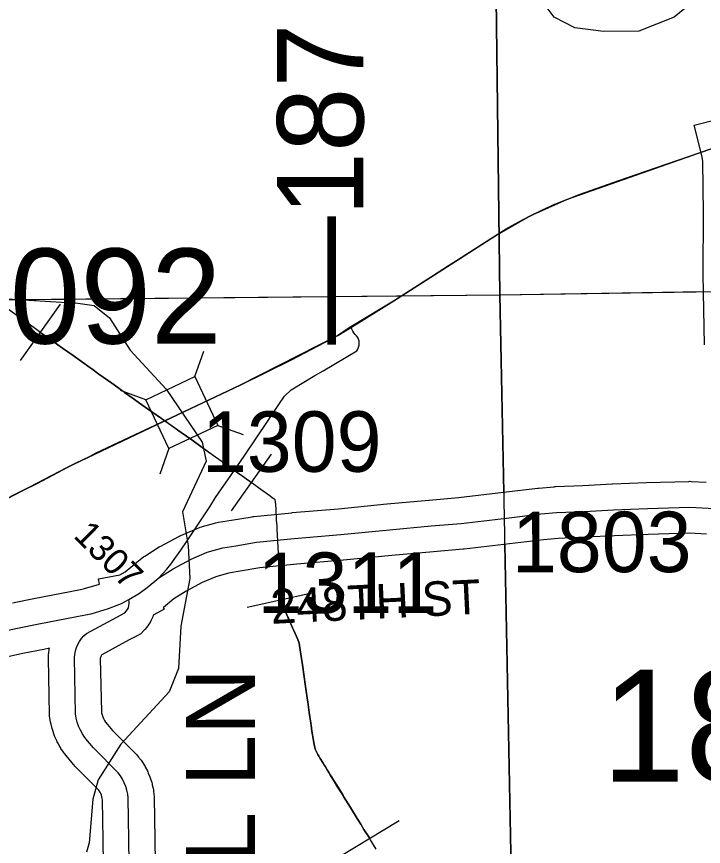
# Model space of a CAD drawing. Extents: x 23.6 to 68.7, y -63 to -29.
# Drawn here: x 50.082 to 50.878, y -48.134 to -47.173 of the extents above; entities that cross this region are included whole.
import ezdxf

# ---------------------------------------------------------------- set-up
doc = ezdxf.new("R2010")
doc.units = 0
for name, color, linetype in [('tdCoHydroRiver', 7, 'Continuous'), ('tdCoPipe', 7, 'Continuous'), ('tdCoPriCL', 7, 'Continuous'), ('tdCoPrimary', 7, 'Continuous'), ('tdCoPriNonDiv', 7, 'Continuous'), ('tdCoPriNonDivCL', 7, 'Continuous'), ('tdCoSecRdNmbr', 7, 'Continuous'), ('tdCoSecRdTxt', 7, 'Continuous'), ('tdCoSecRteBand', 7, 'Continuous'), ('tdCoSecRteCL', 7, 'Continuous'), ('tdCoSectLine', 7, 'Continuous'), ('tdCoSectLinePart', 7, 'Continuous'), ('tdCoSectNmbr', 7, 'Continuous'), ('tdCoStrucNonDivPri', 7, 'Continuous'), ('tdCoStrucPriMaintName', 7, 'Continuous'), ('tdCoSurfConc', 7, 'Continuous'), ('tdCoSurfGravel', 7, 'Continuous'), ('tdCoSurfLNO', 7, 'Continuous'), ('tdCoTwpBndry', 7, 'Continuous'), ('tdCoTwpBndryShd', 7, 'Continuous'), ('tdStHwyPriRefPost1', 7, 'Continuous')]:
    doc.layers.add(name, color=color, linetype=linetype)

msp = doc.modelspace()

# ---------------------------------------------------------------- linework, layer by layer
at = {"layer": 'tdCoHydroRiver'}
for points in [[(51.1423, -46.99481), (51.13769, -47.00591), (50.92232, -47.0872), (50.89892, -47.11272), (50.88345, -47.1413), (50.84434, -47.1733), (50.80347, -47.18954), (50.76244, -47.18998), (50.72924, -47.18561), (50.70543, -47.17325), (50.6846, -47.14506), (50.67644, -47.12148), (50.67296, -47.09152), (50.65707, -47.08222), (50.56834, -47.05163), (50.52706, -47.02998), (50.45691, -46.96603), (50.4504, -46.94873), (50.44838, -46.90772), (50.45412, -46.85556), (50.46586, -46.77493)], [(50.05228, -47.06203), (50.06018, -47.49604), (50.06495, -47.49915), (50.15341, -47.50449), (50.17238, -47.50744), (50.1899, -47.52146), (50.21399, -47.55907), (50.25553, -47.6044), (50.29723, -47.6655), (50.30221, -47.68755), (50.27444, -47.74626), (50.28119, -47.78564), (50.28318, -47.82351), (50.27274, -47.87888), (50.27012, -47.92784), (50.25936, -47.95479), (50.20319, -48.01539), (50.17681, -48.05673), (50.17074, -48.07889), (50.16656, -48.12945), (50.16352, -48.14053)]]:
    msp.add_lwpolyline(points, dxfattribs=at)
at = {"layer": 'tdCoPipe'}
for p, q in [((50.08689, -47.57116), (50.13336, -47.50583)), ((50.3315, -47.74522), (50.3776, -47.67963)), ((50.3497, -47.8567), (50.42797, -47.83933)), ((50.4572, -48.14523), (50.52579, -48.10374))]:
    msp.add_line(p, q, dxfattribs=at)
for points in [[(50.49895, -48.13678), (50.49603, -48.13187), (50.49253, -48.12631), (50.49115, -48.12403), (50.48487, -48.11405), (50.48125, -48.10806), (50.4771, -48.1013), (50.4692, -48.08859), (50.46127, -48.07592), (50.46065, -48.07486), (50.45479, -48.06536), (50.44963, -48.05703), (50.44696, -48.05262), (50.44585, -48.05079), (50.44432, -48.04823), (50.44232, -48.04509), (50.44019, -48.0416), (50.43912, -48.03998), (50.43767, -48.03755), (50.4342, -48.03185), (50.43267, -48.02938), (50.43132, -48.02726), (50.42819, -48.0212), (50.42663, -48.0137), (50.42626, -48.01127), (50.42461, -48.00038), (50.42359, -47.99341), (50.42323, -47.99098), (50.4215, -47.97876), (50.41973, -47.96625), (50.4194, -47.96438), (50.41755, -47.95141), (50.41678, -47.94597), (50.41558, -47.9372), (50.41359, -47.92341), (50.41145, -47.90877), (50.4098, -47.89827), (50.40815, -47.89421), (50.40355, -47.8838), (50.40212, -47.88048), (50.40021, -47.87612), (50.39762, -47.87021), (50.39673, -47.86812), (50.39135, -47.85568), (50.3895, -47.85132), (50.38778, -47.84356), (50.38736, -47.84141), (50.3865, -47.83684), (50.38635, -47.82653), (50.38631, -47.8222), (50.38632, -47.81203), (50.38628, -47.80882), (50.38607, -47.80061), (50.38579, -47.79401), (50.38514, -47.78075), (50.38445, -47.76618), (50.3843, -47.76254), (50.38373, -47.75575), (50.38349, -47.75121), (50.3832, -47.74577), (50.38302, -47.74264), (50.38256, -47.73429), (50.38207, -47.73249), (50.38104, -47.73155), (50.37823, -47.72954), (50.37477, -47.72704), (50.37211, -47.72517), (50.36704, -47.72159), (50.35519, -47.71295), (50.34355, -47.70478), (50.33251, -47.69689), (50.32058, -47.68819), (50.30909, -47.68012), (50.29725, -47.67167), (50.28531, -47.66293), (50.27308, -47.65438), (50.26167, -47.6463), (50.25017, -47.63814), (50.23895, -47.63038), (50.22742, -47.62235), (50.21615, -47.61424), (50.20741, -47.60797), (50.20571, -47.60673), (50.20135, -47.60359), (50.19103, -47.59617), (50.18914, -47.59485), (50.18766, -47.59382), (50.17766, -47.58672), (50.16948, -47.58085), (50.16717, -47.57922), (50.15746, -47.57226), (50.14777, -47.5653), (50.13556, -47.55665), (50.12331, -47.54795), (50.11206, -47.53995), (50.10257, -47.5332), (50.09466, -47.52757), (50.08249, -47.51888), (50.07032, -47.5102)], [(50.11012, -47.53849), (50.1121, -47.5399), (50.12335, -47.5479), (50.1356, -47.5566), (50.14781, -47.56524), (50.1575, -47.57221), (50.16721, -47.57916), (50.16952, -47.5808), (50.17769, -47.58667), (50.1877, -47.59377), (50.18917, -47.5948), (50.19107, -47.59611), (50.20139, -47.60353), (50.20574, -47.60668), (50.20745, -47.60791), (50.21619, -47.61419), (50.22746, -47.62229), (50.23899, -47.63033), (50.25021, -47.63809), (50.26171, -47.64624), (50.27312, -47.65433), (50.28535, -47.66288), (50.29729, -47.67162), (50.30913, -47.68006), (50.32062, -47.68814), (50.33254, -47.69683), (50.34359, -47.70472), (50.35455, -47.71242)], [(50.38884, -47.84801), (50.38956, -47.8513), (50.39141, -47.85565), (50.39679, -47.8681), (50.39768, -47.87018), (50.40027, -47.8761), (50.40218, -47.88046), (50.40361, -47.88377), (50.40821, -47.89418), (50.40987, -47.89825), (50.41152, -47.90876), (50.41366, -47.9234), (50.41565, -47.93719), (50.41685, -47.94596), (50.41762, -47.9514), (50.41947, -47.96437), (50.41979, -47.96624), (50.42156, -47.97876), (50.4233, -47.99097), (50.42365, -47.9934), (50.42468, -48.00037), (50.42633, -48.01126), (50.4267, -48.01368), (50.42826, -48.02117), (50.43138, -48.02722), (50.43273, -48.02935), (50.43426, -48.03182), (50.43773, -48.03752), (50.43918, -48.03995), (50.44024, -48.04157), (50.44238, -48.04505), (50.44438, -48.0482), (50.44591, -48.05075), (50.44702, -48.05259), (50.44969, -48.057), (50.45485, -48.06532), (50.4607, -48.07483), (50.46133, -48.07588), (50.46926, -48.08856), (50.47715, -48.10127), (50.4813, -48.10802), (50.48493, -48.11401), (50.4912, -48.124), (50.4915, -48.12449)]]:
    msp.add_lwpolyline(points, dxfattribs=at)
at = {"layer": 'tdCoPriCL'}
msp.add_lwpolyline([(50.07612, -47.7283), (50.08989, -47.72127), (50.10642, -47.71289), (50.14045, -47.69488), (50.16751, -47.68164), (50.17473, -47.67811), (50.22562, -47.65408), (50.25463, -47.64038), (50.34193, -47.5992), (50.40062, -47.5701), (50.45413, -47.54223), (50.46063, -47.53822), (50.4678, -47.53262), (50.47004, -47.53241), (50.51924, -47.50204), (50.5344, -47.4922), (50.55647, -47.47787), (50.58294, -47.46101), (50.59519, -47.45321), (50.63194, -47.42953), (50.64012, -47.42453), (50.64969, -47.41868), (50.66346, -47.4109), (50.67746, -47.40355), (50.69168, -47.39662), (50.7061, -47.39013), (50.72072, -47.38409), (50.73551, -47.37849), (50.78015, -47.36246), (50.81171, -47.35161), (50.88668, -47.32596)], dxfattribs=at)
at = {"layer": 'tdCoPrimary'}
for p, q in [((50.21302, -47.66021), (50.226, -47.65408)), ((50.21302, -47.66021), (50.226, -47.65408)), ((50.15169, -47.68957), (50.16789, -47.68164)), ((50.15169, -47.68957), (50.16789, -47.68164))]:
    msp.add_line(p, q, dxfattribs=at)
for points in [[(50.54311, -47.48679), (50.55685, -47.47787), (50.59557, -47.45321), (50.63231, -47.42953), (50.65007, -47.41868), (50.66384, -47.4109), (50.67784, -47.40355), (50.69206, -47.39662), (50.70648, -47.39013), (50.7211, -47.38409), (50.73589, -47.37849), (50.78052, -47.36246), (50.81209, -47.35161), (50.88706, -47.32596), (50.90383, -47.32029), (50.93885, -47.30845), (51.00346, -47.28626), (51.05697, -47.26776), (51.10654, -47.25099), (51.18743, -47.22238), (51.25929, -47.19766), (51.26412, -47.196), (51.27514, -47.19215)], [(50.54311, -47.48679), (50.55685, -47.47787), (50.59557, -47.45321), (50.63231, -47.42953), (50.65007, -47.41868), (50.66384, -47.4109), (50.67784, -47.40355), (50.69206, -47.39662), (50.70648, -47.39013), (50.7211, -47.38409), (50.73589, -47.37849), (50.78052, -47.36246), (50.81209, -47.35161), (50.88706, -47.32596), (50.90383, -47.32029), (50.93885, -47.30845), (51.00346, -47.28626), (51.05697, -47.26776), (51.10654, -47.25099), (51.18743, -47.22238), (51.25929, -47.19766), (51.26412, -47.196), (51.27514, -47.19215)], [(50.0765, -47.7283), (50.09027, -47.72127), (50.1068, -47.71289), (50.14083, -47.69488), (50.15169, -47.68957), (50.16789, -47.68164), (50.17511, -47.67811), (50.21302, -47.66021), (50.226, -47.65408), (50.25501, -47.64038), (50.3423, -47.5992), (50.401, -47.5701), (50.45451, -47.54223), (50.47042, -47.53241), (50.51961, -47.50204), (50.54311, -47.48679), (50.55685, -47.47787), (50.59557, -47.45321), (50.63231, -47.42953), (50.65007, -47.41868), (50.66384, -47.4109), (50.67784, -47.40355), (50.69206, -47.39662), (50.70648, -47.39013), (50.7211, -47.38409), (50.73589, -47.37849), (50.78052, -47.36246), (50.81209, -47.35161), (50.88706, -47.32596)], [(50.226, -47.65408), (50.25501, -47.64038), (50.3423, -47.5992), (50.401, -47.5701), (50.45451, -47.54223), (50.47042, -47.53241), (50.51961, -47.50204), (50.54311, -47.48679)], [(50.226, -47.65408), (50.25501, -47.64038), (50.3423, -47.5992), (50.401, -47.5701), (50.45451, -47.54223), (50.47042, -47.53241), (50.51961, -47.50204), (50.54311, -47.48679)], [(50.16789, -47.68164), (50.17511, -47.67811), (50.21302, -47.66021)], [(50.16789, -47.68164), (50.17511, -47.67811), (50.21302, -47.66021)], [(49.90289, -47.83922), (49.98004, -47.78785), (50.02295, -47.75925), (50.03609, -47.7511), (50.0494, -47.74322), (50.06287, -47.73562), (50.0765, -47.7283), (50.09027, -47.72127), (50.1068, -47.71289), (50.14083, -47.69488), (50.15169, -47.68957)], [(49.90289, -47.83922), (49.98004, -47.78785), (50.02295, -47.75925), (50.03609, -47.7511), (50.0494, -47.74322), (50.06287, -47.73562), (50.0765, -47.7283), (50.09027, -47.72127), (50.1068, -47.71289), (50.14083, -47.69488), (50.15169, -47.68957)]]:
    msp.add_lwpolyline(points, dxfattribs=at)
at = {"layer": 'tdCoPriNonDiv'}
msp.add_lwpolyline([(49.39204, -48.17452), (49.68155, -47.9834), (49.87637, -47.85665), (50.02261, -47.75924), (50.06253, -47.73561), (50.14049, -47.69487), (50.34196, -47.59919), (50.45417, -47.54222), (50.46784, -47.53261), (50.51927, -47.50203), (50.63197, -47.42953), (50.6775, -47.40354), (50.72076, -47.38408), (50.88672, -47.32595), (51.1062, -47.25098), (51.30472, -47.18169), (51.40583, -47.15012), (51.66353, -47.06109)], dxfattribs=at)
at = {"layer": 'tdCoPriNonDivCL'}
msp.add_lwpolyline([(50.07612, -47.7283), (50.08989, -47.72127), (50.10642, -47.71289), (50.14045, -47.69488), (50.15131, -47.68957), (50.16751, -47.68164), (50.17473, -47.67811), (50.21264, -47.66021), (50.22562, -47.65408), (50.25463, -47.64038), (50.34193, -47.5992), (50.40062, -47.5701), (50.45413, -47.54223), (50.47004, -47.53241), (50.51924, -47.50204), (50.54273, -47.48679), (50.55647, -47.47787), (50.59519, -47.45321), (50.63194, -47.42953), (50.64969, -47.41868), (50.66346, -47.4109), (50.67746, -47.40355), (50.69168, -47.39662), (50.7061, -47.39013), (50.72072, -47.38409), (50.73551, -47.37849), (50.78015, -47.36246), (50.81171, -47.35161), (50.88668, -47.32596)], dxfattribs=at)
msp.add_lwpolyline([(50.07612, -47.7283), (50.08989, -47.72127), (50.10642, -47.71289), (50.14045, -47.69488), (50.15131, -47.68957), (50.16751, -47.68164), (50.17473, -47.67811), (50.21264, -47.66021), (50.22562, -47.65408), (50.25463, -47.64038), (50.34193, -47.5992), (50.40062, -47.5701), (50.45413, -47.54223), (50.47004, -47.53241), (50.51924, -47.50204), (50.54273, -47.48679), (50.55647, -47.47787), (50.59519, -47.45321), (50.63194, -47.42953), (50.64969, -47.41868), (50.66346, -47.4109), (50.67746, -47.40355), (50.69168, -47.39662), (50.7061, -47.39013), (50.72072, -47.38409), (50.73551, -47.37849), (50.78015, -47.36246), (50.81171, -47.35161), (50.88668, -47.32596)], dxfattribs=at)
at = {"layer": 'tdCoSecRteBand'}
for points in [[(50.87945, -47.55282), (50.87814, -47.47145), (50.87813, -47.47112), (50.87813, -47.4708), (50.87851, -47.40034), (50.87757, -47.34041), (50.87669, -47.33542), (50.87472, -47.32756), (50.86745, -47.29846), (50.92566, -47.28391)], [(50.07755, -47.85162), (50.10221, -47.84669), (50.10234, -47.84666), (50.10247, -47.84664), (50.15624, -47.83637), (50.16123, -47.83525), (50.17847, -47.82997), (50.1773, -47.82386), (50.20186, -47.81916), (50.20812, -47.81558), (50.21486, -47.81037), (50.22803, -47.7996), (50.22943, -47.79846), (50.23096, -47.7975), (50.24756, -47.78697), (50.24849, -47.78639), (50.24946, -47.78587), (50.27034, -47.77469), (50.27151, -47.77406), (50.27274, -47.77354), (50.29165, -47.76548), (50.29338, -47.76474), (50.2952, -47.76422), (50.31312, -47.75913), (50.31479, -47.75865), (50.3165, -47.75837), (50.33159, -47.75591), (50.35539, -47.75197), (50.35633, -47.75182), (50.35727, -47.75172), (50.40117, -47.74728), (50.4014, -47.74726), (50.40164, -47.74724), (50.45552, -47.74265), (50.51153, -47.73709), (50.51169, -47.73707), (50.51186, -47.73706), (50.56019, -47.73278), (50.56023, -47.73278), (50.56027, -47.73277), (50.59431, -47.72986), (50.64642, -47.72367), (50.68636, -47.7189), (50.68678, -47.71885), (50.6872, -47.71881), (50.70529, -47.71717), (50.70603, -47.7171), (50.70677, -47.71707), (50.73865, -47.71576), (50.77233, -47.71396), (50.77257, -47.71395), (50.77281, -47.71394), (50.81226, -47.71246), (50.81237, -47.71246), (50.81248, -47.71246), (50.86147, -47.71098), (50.86269, -47.71094), (50.86391, -47.711), (50.88151, -47.7119)], [(50.882, -47.772), (50.86207, -47.77099), (50.8144, -47.77243), (50.77529, -47.77389), (50.74166, -47.77569), (50.74148, -47.7757), (50.74129, -47.77571), (50.70998, -47.77699), (50.69306, -47.77853), (50.65352, -47.78325), (50.65352, -47.78325), (50.65351, -47.78325), (50.6009, -47.7895), (50.60041, -47.78955), (50.59992, -47.7896), (50.56544, -47.79255), (50.51731, -47.79681), (50.46124, -47.80238), (50.46103, -47.8024), (50.46082, -47.80242), (50.40697, -47.807), (50.36425, -47.81132), (50.34135, -47.81511), (50.34131, -47.81512), (50.34128, -47.81513), (50.32786, -47.81731), (50.31343, -47.82142), (50.29748, -47.82821), (50.27875, -47.83824), (50.2646, -47.84721), (50.25251, -47.85708), (50.25239, -47.85719), (50.25334, -47.85885), (50.24152, -47.8656), (50.24062, -47.86611), (50.24007, -47.868), (50.23906, -47.87014), (50.23801, -47.87235), (50.23699, -47.87449), (50.23565, -47.87645), (50.23427, -47.87847), (50.23293, -47.88043), (50.2313, -47.88215), (50.22962, -47.88392), (50.22628, -47.88744), (50.22201, -47.88973), (50.21284, -47.89464), (50.18117, -47.91173), (50.18066, -47.91245), (50.18022, -47.91324), (50.17986, -47.91406), (50.17959, -47.91492), (50.17941, -47.9158), (50.17934, -47.91653), (50.18058, -47.97754), (50.18083, -47.97917), (50.1814, -47.98145), (50.18216, -47.98367), (50.18312, -47.98582), (50.18426, -47.98787), (50.18557, -47.98982), (50.18775, -47.99249), (50.19355, -47.99943), (50.22128, -48.02748), (50.22265, -48.02886), (50.22383, -48.03041), (50.22659, -48.03404), (50.22739, -48.03509), (50.22809, -48.03621), (50.23052, -48.04006), (50.23122, -48.04118), (50.23183, -48.04235), (50.23391, -48.04641), (50.23451, -48.04758), (50.23501, -48.04881), (50.23673, -48.05303), (50.23722, -48.05425), (50.23761, -48.05551), (50.23895, -48.05987), (50.23934, -48.06113), (50.23962, -48.06242), (50.24057, -48.06688), (50.24084, -48.06817), (50.241, -48.06948), (50.24156, -48.07401), (50.24175, -48.07558), (50.24178, -48.07716), (50.2426, -48.12533), (50.2426, -48.12538), (50.2426, -48.12542), (50.24376, -48.20779)], [(50.18376, -48.2086), (50.18261, -48.12631), (50.18182, -48.07976), (50.18161, -48.07812), (50.18121, -48.07625), (50.18065, -48.07441), (50.17993, -48.07264), (50.17905, -48.07093), (50.17803, -48.06931), (50.17725, -48.06828), (50.15001, -48.04073), (50.14913, -48.03984), (50.14833, -48.03889), (50.14159, -48.03083), (50.14145, -48.03067), (50.14132, -48.0305), (50.13817, -48.02663), (50.13734, -48.0256), (50.1366, -48.02451), (50.13381, -48.02038), (50.13307, -48.01929), (50.13243, -48.01813), (50.13001, -48.01377), (50.12937, -48.01262), (50.12884, -48.01142), (50.12681, -48.00686), (50.12627, -48.00565), (50.12584, -48.00441), (50.12422, -47.99969), (50.1238, -47.99844), (50.12348, -47.99716), (50.12228, -47.99232), (50.12196, -47.99104), (50.12176, -47.98974), (50.12099, -47.98481), (50.12067, -47.98281), (50.12063, -47.98079), (50.11932, -47.91601), (50.11928, -47.91428), (50.11945, -47.91255), (50.11983, -47.90853), (50.11998, -47.90696), (50.12029, -47.90543), (50.12053, -47.90427), (50.11385, -47.90555), (50.08952, -47.91041), (50.06881, -47.91486)]]:
    msp.add_lwpolyline(points, dxfattribs=at)
at = {"layer": 'tdCoSecRteCL'}
for points in [[(50.21241, -47.84769), (50.22482, -47.84059), (50.23353, -47.83385), (50.24701, -47.82284), (50.26362, -47.81231), (50.2845, -47.80113), (50.3034, -47.79308), (50.32132, -47.78798), (50.33645, -47.78552), (50.36029, -47.78157), (50.40418, -47.77713), (50.45827, -47.77253), (50.5145, -47.76694), (50.56284, -47.76266), (50.59736, -47.75971), (50.64997, -47.75346), (50.68992, -47.74869), (50.708, -47.74705), (50.74006, -47.74573), (50.77393, -47.74392), (50.81339, -47.74244), (50.86238, -47.74096), (50.89789, -47.74277), (50.91179, -47.74672)], [(49.90661, -47.97943), (49.91212, -47.97573), (49.93152, -47.96077), (49.94665, -47.94828), (49.96736, -47.93151), (49.98298, -47.92066), (49.99515, -47.91277), (50.0037, -47.90783), (50.01455, -47.9029), (50.03411, -47.89452), (50.04414, -47.89106), (50.06124, -47.8858), (50.08343, -47.88104), (50.10809, -47.8761), (50.16235, -47.86575), (50.16892, -47.86427), (50.18881, -47.85818), (50.2041, -47.85243), (50.21241, -47.84769)], [(50.21376, -48.20821), (50.21261, -48.12584), (50.21179, -48.07767), (50.21123, -48.07315), (50.21028, -48.06869), (50.20894, -48.06433), (50.20722, -48.06011), (50.20514, -48.05606), (50.20271, -48.0522), (50.19995, -48.04857), (50.17134, -48.01964), (50.1646, -48.01158), (50.16146, -48.00771), (50.15866, -48.00358), (50.15624, -47.99922), (50.15422, -47.99466), (50.1526, -47.98995), (50.1514, -47.98511), (50.15063, -47.98018), (50.14931, -47.9154), (50.1497, -47.91138), (50.1505, -47.90742), (50.15171, -47.90357), (50.15332, -47.89986), (50.1553, -47.89635), (50.15764, -47.89305), (50.16031, -47.89002), (50.16329, -47.88729), (50.19863, -47.86822), (50.20784, -47.86329), (50.20952, -47.86151), (50.2109, -47.8595), (50.21195, -47.85729), (50.21263, -47.85495), (50.21294, -47.85253), (50.21286, -47.85008), (50.21241, -47.84769)]]:
    msp.add_lwpolyline(points, dxfattribs=at)
at = {"layer": 'tdCoSectLine'}
for points in [[(50.62998, -46.49618), (50.64249, -47.49486)], [(50.64249, -47.49486), (51.65283, -47.47956)], [(49.64392, -47.50485), (50.64249, -47.49486)], [(50.64249, -47.49486), (50.66183, -48.48832)]]:
    msp.add_lwpolyline(points, dxfattribs=at)
at = {"layer": 'tdCoSectLinePart'}
for points in [[(50.62998, -46.49618), (50.64249, -47.49486)], [(49.92253, -47.50206), (50.64249, -47.49486)], [(50.64249, -47.49486), (50.87808, -47.49129)], [(50.64249, -47.49486), (50.64695, -47.7238)], [(50.64812, -47.78402), (50.66125, -48.45863)]]:
    msp.add_lwpolyline(points, dxfattribs=at)
at = {"layer": 'tdCoStrucNonDivPri'}
for p, q in [((50.28873, -47.5897), (50.2993, -47.56024)), ((50.23211, -47.61641), (50.20265, -47.60583)), ((50.31544, -47.64631), (50.3449, -47.65689)), ((50.25882, -47.67302), (50.24825, -47.70248))]:
    msp.add_line(p, q, dxfattribs=at)
msp.add_lwpolyline([(50.23211, -47.61641), (50.28873, -47.5897), (50.31544, -47.64631), (50.25882, -47.67302)], close=True, dxfattribs=at)
at = {"layer": 'tdCoSurfConc'}
msp.add_lwpolyline([(50.06124, -47.8858), (50.08343, -47.88104), (50.10809, -47.8761), (50.16235, -47.86575), (50.16892, -47.86427), (50.18881, -47.85818), (50.2041, -47.85243), (50.21241, -47.84769), (50.22482, -47.84059), (50.23353, -47.83385), (50.24701, -47.82284)], dxfattribs=at)
at = {"layer": 'tdCoSurfGravel'}
for points in [[(50.64997, -47.75346), (50.68992, -47.74869), (50.708, -47.74705), (50.74006, -47.74573), (50.77393, -47.74392), (50.81339, -47.74244), (50.86238, -47.74096), (50.89789, -47.74277), (50.91179, -47.74672)], [(50.24701, -47.82284), (50.26362, -47.81231), (50.2845, -47.80113), (50.3034, -47.79308), (50.32132, -47.78798), (50.33645, -47.78552), (50.36029, -47.78157), (50.40418, -47.77713), (50.45827, -47.77253), (50.5145, -47.76694), (50.56284, -47.76266), (50.59736, -47.75971), (50.64997, -47.75346)], [(50.21376, -48.20821), (50.21261, -48.12584), (50.21179, -48.07767), (50.21123, -48.07315), (50.21028, -48.06869), (50.20894, -48.06433), (50.20722, -48.06011), (50.20514, -48.05606), (50.20271, -48.0522), (50.19995, -48.04857), (50.17134, -48.01964), (50.1646, -48.01158), (50.16146, -48.00771), (50.15866, -48.00358), (50.15624, -47.99922), (50.15422, -47.99466), (50.1526, -47.98995), (50.1514, -47.98511), (50.15063, -47.98018), (50.14931, -47.9154), (50.1497, -47.91138), (50.1505, -47.90742), (50.15171, -47.90357), (50.15332, -47.89986), (50.1553, -47.89635), (50.15764, -47.89305), (50.16031, -47.89002), (50.16329, -47.88729), (50.19863, -47.86822), (50.20784, -47.86329), (50.20952, -47.86151), (50.2109, -47.8595), (50.21195, -47.85729), (50.21263, -47.85495), (50.21294, -47.85253), (50.21286, -47.85008), (50.21241, -47.84769)]]:
    msp.add_lwpolyline(points, dxfattribs=at)
at = {"layer": 'tdCoSurfLNO'}
for p, q in [((50.47095, -47.53472), (50.47042, -47.53241)), ((50.47186, -47.53692), (50.47095, -47.53472)), ((50.47311, -47.53894), (50.47186, -47.53692)), ((50.47467, -47.54073), (50.47311, -47.53894)), ((50.47631, -47.54238), (50.47467, -47.54073)), ((50.47765, -47.54429), (50.47631, -47.54238)), ((50.47864, -47.54641), (50.47765, -47.54429)), ((50.47925, -47.54866), (50.47864, -47.54641)), ((50.47947, -47.55098), (50.47925, -47.54866)), ((50.4793, -47.5533), (50.47947, -47.55098)), ((50.43751, -47.58298), (50.47648, -47.55963)), ((50.47648, -47.55963), (50.47778, -47.5577)), ((50.47778, -47.5577), (50.47873, -47.55556)), ((50.47873, -47.55556), (50.4793, -47.5533)), ((50.40069, -47.60501), (50.42798, -47.5884)), ((50.42798, -47.5884), (50.43751, -47.58298)), ((50.39296, -47.61224), (50.40069, -47.60501)), ((50.38622, -47.62178), (50.39296, -47.61224)), ((50.37405, -47.64052), (50.38622, -47.62178)), ((50.3461, -47.68178), (50.37405, -47.64052)), ((50.3272, -47.7094), (50.3461, -47.68178)), ((50.31988, -47.71947), (50.3272, -47.7094)), ((50.31292, -47.72977), (50.31988, -47.71947)), ((50.30632, -47.74031), (50.31292, -47.72977)), ((50.29312, -47.76004), (50.30632, -47.74031)), ((50.28018, -47.77993), (50.29312, -47.76004)), ((50.27277, -47.79073), (50.28018, -47.77993)), ((50.26505, -47.80131), (50.27277, -47.79073)), ((50.26095, -47.80702), (50.26505, -47.80131)), ((50.25192, -47.81779), (50.25656, -47.81252)), ((50.25656, -47.81252), (50.26095, -47.80702)), ((50.24701, -47.82284), (50.25192, -47.81779))]:
    msp.add_line(p, q, dxfattribs=at)
at = {"layer": 'tdCoTwpBndry'}
for points in [[(50.64694, -47.72357), (50.64249, -47.49486), (50.62998, -46.49618), (50.62414, -46.03054)], [(50.66124, -48.45812), (50.64812, -47.78383)]]:
    msp.add_lwpolyline(points, dxfattribs=at)
at = {"layer": 'tdCoTwpBndryShd'}
msp.add_lwpolyline([(50.55093, -40.54435), (50.56393, -41.54268), (50.56896, -42.54168), (50.58705, -43.53699), (50.60187, -44.52882), (50.62028, -45.53266), (50.62998, -46.49618), (50.64249, -47.49486), (50.66183, -48.48832), (50.67787, -49.49067), (50.68743, -50.4863), (50.70608, -51.48633), (50.72291, -52.55727), (50.73763, -53.55285), (50.75291, -54.55987), (50.76815, -55.55139), (50.78515, -56.5511), (50.79735, -57.54718)], dxfattribs=at)

# ---------------------------------------------------------------- texts
at = {"layer": 'tdCoSecRdNmbr'}
for s, height, rotation, p in [('1309', 0.07, 0.03763, (50.29709, -47.70001)), ('1803', 0.07, 0.03931, (50.65631, -47.81621)), ('1307', 0.03, 315.03818, (50.14706, -47.77501)), ('1311', 0.07, 0.03908, (50.36172, -47.86343))]:
    msp.add_text(s, height=height, rotation=rotation, dxfattribs=at).set_placement(p)
at = {"layer": 'tdCoSecRdTxt'}
for s, height, rotation, p in [('248TH ST', 0.04, 2.76464, (50.37756, -47.87605)), ('ROYAL LN', 0.08, 90, (50.35852, -48.45662))]:
    msp.add_text(s, height=height, rotation=rotation, dxfattribs=at).set_placement(p)
at = {"layer": 'tdCoSectNmbr'}
msp.add_text('18', height=0.13, rotation=0.03932, dxfattribs=at).set_placement((50.76033, -48.05898))
at = {"layer": 'tdCoStrucPriMaintName'}
msp.add_text('62868S092', height=0.11, dxfattribs=at).set_placement((49.56734, -47.55139))
msp.add_text('62868S092', height=0.11, dxfattribs=at).set_placement((49.56734, -47.55139))
msp.add_text('62868S092', height=0.11, dxfattribs=at).set_placement((49.56734, -47.55139))
at = {"layer": 'tdStHwyPriRefPost1'}
msp.add_text('‒‒187', height=0.1, rotation=90, dxfattribs=at).set_placement((50.48432, -47.55255))

doc.saveas('drawing.dxf')
